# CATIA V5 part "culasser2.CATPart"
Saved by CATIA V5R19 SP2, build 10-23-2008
Part number: culasser
Bounding box of the stored display mesh (mm): x -110 to 110, y -70 to 70, z -50 to 50
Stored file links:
  C:\Users\marc\Desktop\boulot\Semestre 3\CFAO\Projet CFAO\robuste\culasser2.CATPart
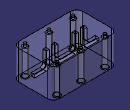
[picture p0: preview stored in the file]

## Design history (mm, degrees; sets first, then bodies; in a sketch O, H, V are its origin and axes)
Parameters
  longculasse = 220 mm
  largculasse = 140 mm
  hautculasse = 100 mm
  raytrouaccess = 10 mm
  raypion = 5 mm
  cotetube = 12 mm
Body1 (main body)
  Sketch1 on xy-plane, origin (0, 0, 0), H (1, 0, 0), V (0, 1, 0)
    line L1 (-110, -70) -> (-110, 70)
    line L2 (-110, 70) -> (110, 70)
    line L3 (110, 70) -> (110, -70)
    line L4 (110, -70) -> (-110, -70)
    distance O L2 = 70 {= largculasse /2}
    distance O L1 = 110 {= longculasse /2}
    length L3 = 140 {= largculasse}
    length L4 = 220 {= longculasse}
    vertical: L1 V, L3 V
    horizontal: L2 H, L4 H
  Pad1: profile Sketch1, direction (0, 0, -1), length 50 {= hautculasse/2}, mirrored extent
  Body2
    Sketch2 on end face of Pad1, origin (0, 0, -50), H (1, 0, 0), V (0, -1, 0)
      circle A1 centre (-82.5, 55) radius 10
      point P1 (-82.5, 55)
      circle A2 centre (82.5, 55) radius 10
      point P2 (82.5, 55)
      circle A3 centre (0, 55) radius 10
      point P3 (0, 55)
      reference projected line E1 (110, 70) -> (-110, 70) from edge [face of Pad1 from Sketch1.L4 | end face of Pad1]
      reference projected line E2 (110, 70) -> (-110, 70) from edge [face of Pad1 from Sketch1.L4 | end face of Pad1]
      reference projected line E3 (110, 70) -> (-110, 70) from edge [face of Pad1 from Sketch1.L4 | end face of Pad1]
      reference projected line E4 (110, -70) -> (110, 70) from edge [face of Pad1 from Sketch1.L3 | end face of Pad1]
      reference projected line E5 (-110, 70) -> (-110, -70) from edge [face of Pad1 from Sketch1.L1 | end face of Pad1]
      reference projected line E6 (110, -70) -> (110, 70) from edge [face of Pad1 from Sketch1.L3 | end face of Pad1]
      radius A1 = 10 {= raytrouaccess}
      radius A2 = 10 {= raytrouaccess}
      radius A3 = 10 {= raytrouaccess}
      distance E1 P1 = 15
      distance P2 E2 = 15
      distance P3 E3 = 15
      distance P2 E4 = 27.5 {= longculasse /8}
      distance E5 P1 = 27.5 {= longculasse /8}
      distance P3 E6 = 110 {= longculasse /2}
    Pad2: profile Sketch2, direction (0, 0, 1), length 90 {= hautculasse -(hautculasse /10)}
    Mirror1: of Pad2, about zx-plane
  Remove1: tool Body2
  Chamfer1: length 2, angle 45, on edge [face of Mirror1 | end face of Pad1] (x3); edge [end face of Pad1 | face of Pad2 from Sketch2.A1]; edge [end face of Pad1 | face of Pad2 from Sketch2.A3]; edge [end face of Pad1 | face of Pad2 from Sketch2.A2]
  Body3
    Sketch3 on end face of Pad1, origin (0, 0, -50), H (1, 0, 0), V (0, -1, 0)
      circle A1 centre (-82.5, -55) radius 5
      circle A2 centre (0, -55) radius 5
      point P2 (0, -55)
      circle A3 centre (82.5, -55) radius 5
      reference projected circle E1 centre (82.5, -55) radius 12 from edge [face of Chamfer1 | end face of Pad1]
      reference projected circle E2 centre (0, -55) radius 12 from edge [face of Chamfer1 | end face of Pad1]
      reference projected circle E3 centre (-82.5, -55) radius 12 from edge [face of Chamfer1 | end face of Pad1]
      radius A1 = 5 {= raypion}
      radius A2 = 5 {= raypion}
      radius A3 = 5 {= raypion}
      coincidence: P2 V
      concentricity: E1 A3, A2 E2, E3 A1
    Pad3: profile Sketch3, direction (0, 0, 1), length 500
    Mirror2: of Pad3, about zx-plane
  Remove2: tool Body3
  Body4
    Sketch4 on zx-plane, origin (0, 0, 0), H (-1, 0, 0), V (0, 0, 1)
      line L1 (-110, -10) -> (-70, -10)
      arc A1 centre (-70, 0) radius 10 from (-70, -10) to (-60, 0) ccw
      point P4 (-60, 0)
      line L2 (-60, 0) -> (-60, 50)
      line L3 (-60, 50) -> (-70, 50)
      line L4 (-70, 50) -> (-70, 10)
      arc A2 centre (-80, 10) radius 10 from (-70, 10) to (-80, 0) cw
      point P9 (-80, 0)
      line L5 (-80, 0) -> (-110, 0)
      line L6 (-110, 0) -> (-110, -10)
      reference projected line E1 (-110, 50) -> (-110, -50) from edge [face of Pad1 from Sketch1.L4 | face of Pad1 from Sketch1.L3]
      distance E1 L4 = 40
      length L3 = 10
      length L2 = 50
      length L1 = 40
      length L5 = 30
      length L6 = 10
      horizontal: L1 H, L3 H
      coincidence: P4 H, P9 A1
      tangency: A1 L1, L2 A1, A2 L4, L5 A2
      vertical: L4 V, L6 V
    Pad4: profile Sketch4, direction (0, 1, 0), length 6 {= cotetube /2}, mirrored extent
    Mirror3: of Pad4, about yz-plane
  Remove3: tool Body4
  Body5
    Sketch5 on zx-plane, origin (0, 0, 0), H (-1, 0, 0), V (0, 0, 1)
      line L1 (-40, 50) -> (-40, 0)
      arc A1 centre (-30, 0) radius 10 from (-40, 0) to (-30, -10) ccw
      line L2 (-30, -10) -> (30, -10)
      arc A2 centre (30, 0) radius 10 from (30, -10) to (40, 0) ccw
      line L3 (40, 0) -> (40, 50)
      line L4 (40, 50) -> (30, 50)
      line L5 (30, 50) -> (30, 10)
      point P10 (30, 10)
      arc A3 centre (20, 10) radius 10 from (30, 10) to (20, 0) cw
      point P12 (20, 0)
      line L6 (20, 0) -> (-20, 0)
      point P13 (-20, 0)
      arc A4 centre (-20, 10) radius 10 from (-20, 0) to (-30, 10) cw
      line L7 (-30, 10) -> (-30, 50)
      line L8 (-30, 50) -> (-40, 50)
      vertical: L1 V, L5 V
      tangency: A1 L1, L2 A1, A2 L2, L3 A2, A3 L5, L6 A3, A4 L6, L7 A4
      horizontal: L4 H, L8 H
      coincidence: P10 A2, P12 H, P13 A1
    Pad5: profile Sketch5, direction (0, 1, 0), length 6 {= cotetube /2}, mirrored extent
  Remove4: tool Body5
  Fillet1: radius 20, on edge [face of Pad1 from Sketch1.L2 | face of Pad1 from Sketch1.L1]; edge [face of Pad1 from Sketch1.L3 | face of Pad1 from Sketch1.L2]; edge [face of Pad1 from Sketch1.L4 | face of Pad1 from Sketch1.L3]; edge [face of Pad1 from Sketch1.L1 | face of Pad1 from Sketch1.L4]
